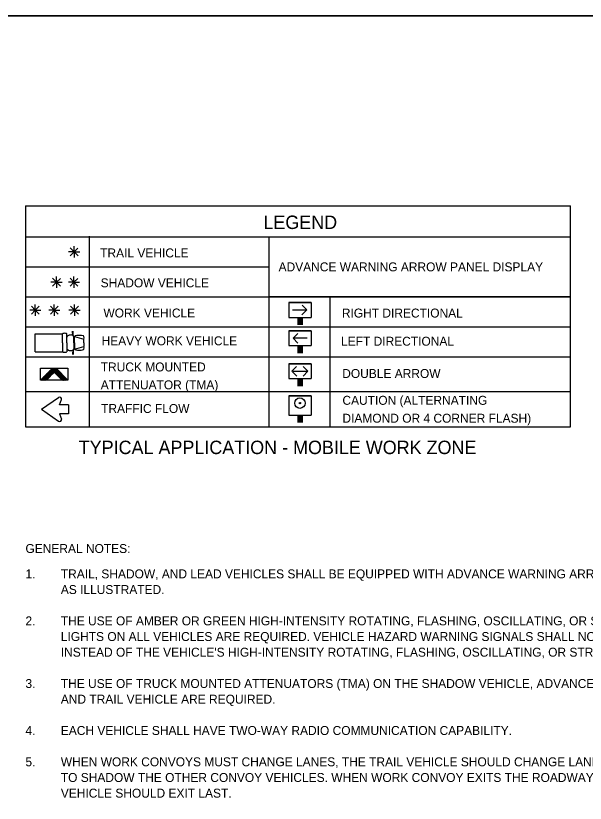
# Model space of a CAD drawing. Extents: x 1416408 to 1429341, y 372694 to 383211.
# Drawn here: x 1428120 to 1428760, y 373596 to 374480 of the extents above; entities that cross this region are included whole.
import ezdxf

# ---------------------------------------------------------------- set-up
doc = ezdxf.new("R2010")
doc.units = 0
for name, color, linetype in [('Default', 7, 'Continuous'), ('DSN_DRFT_Junk-No-Plot', 7, 'Continuous'), ('Working Level 1', 7, 'Continuous')]:
    doc.layers.add(name, color=color, linetype=linetype)

msp = doc.modelspace()

# ---------------------------------------------------------------- linework, layer by layer
at = {"layer": 'Default'}
for points in [[(1426234.86, 374479.9), (1426234.86, 372693.86), (1428995.11, 372693.86), (1428995.11, 374479.9)], [(1426234.86, 374479.9), (1426234.86, 372693.86), (1428995.11, 372693.86), (1428995.11, 374479.9)], [(1426234.86, 374479.9), (1428995.11, 374479.9), (1428995.11, 372693.86), (1426234.86, 372693.86)], [(1426234.86, 374479.9), (1426234.86, 372693.86), (1428995.11, 372693.86), (1428995.11, 374479.9)]]:
    msp.add_lwpolyline(points, close=True, dxfattribs=at)
at = {"layer": 'DSN_DRFT_Junk-No-Plot'}
msp.add_lwpolyline([(1426234.86, 374479.9), (1428995.11, 374479.9), (1428995.11, 372693.86), (1426234.86, 372693.86)], close=True, dxfattribs=at)
at = {"layer": 'Working Level 1'}
for p, q in [((1428130.66, 374266.62), (1428130.66, 374018.44)), ((1428130.66, 374266.62), (1428742.89, 374266.62)), ((1428742.89, 374018.44), (1428742.89, 374266.62)), ((1428130.66, 374231.78), (1428742.89, 374231.78)), ((1428202.33, 374232.37), (1428202.33, 374018.44)), ((1428202.33, 374232.37), (1428202.33, 374018.44)), ((1428404, 374231.78), (1428404, 374018.44)), ((1428185.42, 374214.79), (1428181.01, 374219.25)), ((1428185.31, 374214.71), (1428189.72, 374219.16)), ((1428185.42, 374214.79), (1428185.42, 374221.1)), ((1428185.42, 374214.79), (1428179.18, 374214.79)), ((1428185.42, 374214.79), (1428181.01, 374210.34)), ((1428185.42, 374214.79), (1428189.82, 374210.34)), ((1428185.42, 374214.79), (1428185.42, 374208.5)), ((1428185.42, 374214.79), (1428191.64, 374214.79)), ((1428130.66, 374198.11), (1428404, 374198.11)), ((1428165.58, 374180.75), (1428161.18, 374185.21)), ((1428165.49, 374180.66), (1428169.91, 374185.12)), ((1428165.58, 374180.75), (1428165.58, 374187.06)), ((1428185.18, 374180.75), (1428180.76, 374185.21)), ((1428185.09, 374180.67), (1428189.5, 374185.12)), ((1428185.18, 374180.75), (1428185.18, 374187.06)), ((1428165.58, 374180.75), (1428159.35, 374180.76)), ((1428165.58, 374180.75), (1428161.18, 374176.3)), ((1428165.58, 374180.75), (1428169.99, 374176.3)), ((1428165.58, 374180.75), (1428165.58, 374174.46)), ((1428165.58, 374180.75), (1428171.82, 374180.75)), ((1428185.18, 374180.75), (1428178.95, 374180.75)), ((1428185.18, 374180.75), (1428180.77, 374176.3)), ((1428185.18, 374180.75), (1428189.58, 374176.3)), ((1428185.18, 374180.75), (1428185.18, 374174.46)), ((1428185.18, 374180.75), (1428191.4, 374180.75)), ((1428130.66, 374164.45), (1428742.89, 374164.45)), ((1428742.89, 374164.45), (1428404, 374164.45)), ((1428472.51, 374164.45), (1428472.51, 374018.44)), ((1428141.72, 374149.38), (1428141.72, 374155.68)), ((1428163.08, 374149.38), (1428163.08, 374155.68)), ((1428185.82, 374149.38), (1428185.82, 374155.68)), ((1428426.57, 374157.92), (1428426.57, 374141.26)), ((1428451.5, 374157.92), (1428426.57, 374157.92)), ((1428426.57, 374157.92), (1428451.49, 374157.92)), ((1428451.5, 374157.92), (1428451.5, 374141.26)), ((1428141.72, 374149.38), (1428135.49, 374149.38)), ((1428141.72, 374149.38), (1428137.31, 374153.84)), ((1428141.72, 374149.38), (1428137.32, 374144.93)), ((1428141.63, 374149.28), (1428146.03, 374153.75)), ((1428141.72, 374149.38), (1428146.12, 374144.93)), ((1428141.72, 374149.38), (1428141.72, 374143.08)), ((1428141.72, 374149.38), (1428147.96, 374149.38)), ((1428163.08, 374149.38), (1428156.84, 374149.38)), ((1428163.08, 374149.38), (1428158.65, 374153.84)), ((1428163.08, 374149.38), (1428158.66, 374144.93)), ((1428162.98, 374149.28), (1428167.38, 374153.75)), ((1428163.08, 374149.38), (1428167.47, 374144.93)), ((1428163.08, 374149.38), (1428163.08, 374143.08)), ((1428163.08, 374149.38), (1428169.3, 374149.38)), ((1428185.82, 374149.38), (1428179.6, 374149.38)), ((1428185.82, 374149.38), (1428181.42, 374153.84)), ((1428185.82, 374149.38), (1428181.42, 374144.93)), ((1428185.73, 374149.28), (1428190.15, 374153.75)), ((1428185.82, 374149.38), (1428190.24, 374144.93)), ((1428185.82, 374149.38), (1428185.82, 374143.08)), ((1428185.82, 374149.38), (1428192.05, 374149.38)), ((1428430.79, 374149.6), (1428446.74, 374149.6)), ((1428446.74, 374149.6), (1428441.32, 374144.11)), ((1428446.74, 374149.6), (1428441.45, 374154.94)), ((1428426.57, 374141.26), (1428451.5, 374141.26)), ((1428436.54, 374141.26), (1428436.54, 374132.77)), ((1428437.78, 374141.26), (1428437.78, 374132.77)), ((1428439.03, 374141.26), (1428439.03, 374132.77)), ((1428440.28, 374141.26), (1428440.28, 374132.77)), ((1428441.53, 374141.26), (1428441.53, 374132.77)), ((1428130.66, 374130.78), (1428742.89, 374130.78)), ((1428130.66, 374130.78), (1428403.88, 374130.78)), ((1428141.72, 374122.81), (1428172.44, 374122.81)), ((1428141.72, 374102.72), (1428141.72, 374122.81)), ((1428172.44, 374112.76), (1428172.44, 374122.81)), ((1428177.15, 374112.76), (1428177.15, 374122.81)), ((1428183.49, 374123.4), (1428183.49, 374125.85)), ((1428183.88, 374121.03), (1428183.88, 374125.85)), ((1428184.2, 374121.03), (1428184.2, 374125.85)), ((1428426.57, 374126.21), (1428426.57, 374109.56)), ((1428451.5, 374126.21), (1428426.57, 374126.21)), ((1428426.57, 374126.21), (1428451.49, 374126.21)), ((1428431.32, 374117.89), (1428436.62, 374123.23)), ((1428451.5, 374126.21), (1428451.5, 374109.56)), ((1428172.44, 374112.76), (1428172.44, 374102.72)), ((1428177.15, 374112.76), (1428177.15, 374102.72)), ((1428185.05, 374112.76), (1428185.05, 374119.99)), ((1428185.05, 374112.76), (1428185.05, 374105.53)), ((1428185.69, 374119.99), (1428196.44, 374117.03)), ((1428185.69, 374112.76), (1428185.69, 374119.99)), ((1428185.69, 374112.76), (1428185.69, 374105.53)), ((1428196.44, 374112.76), (1428196.44, 374117.03)), ((1428196.44, 374112.76), (1428196.44, 374108.49)), ((1428447.27, 374117.89), (1428431.32, 374117.89)), ((1428431.32, 374117.89), (1428436.74, 374112.41)), ((1428141.72, 374102.72), (1428172.44, 374102.72)), ((1428183.88, 374104.48), (1428183.88, 374099.66)), ((1428184.2, 374104.48), (1428184.2, 374099.66)), ((1428185.69, 374105.53), (1428196.44, 374108.49)), ((1428426.57, 374109.56), (1428451.5, 374109.56)), ((1428436.54, 374109.56), (1428436.54, 374101.06)), ((1428437.78, 374109.56), (1428437.78, 374101.06)), ((1428439.03, 374109.56), (1428439.03, 374101.06)), ((1428440.28, 374109.56), (1428440.28, 374101.06)), ((1428441.53, 374109.56), (1428441.53, 374101.06)), ((1428130.66, 374097.11), (1428742.89, 374097.11)), ((1428183.49, 374102.13), (1428183.49, 374099.66)), ((1428426.57, 374089.23), (1428426.57, 374072.57)), ((1428451.5, 374089.23), (1428426.57, 374089.23)), ((1428426.57, 374089.23), (1428451.49, 374089.23)), ((1428430.07, 374080.9), (1428435.37, 374086.24)), ((1428447.99, 374080.9), (1428442.69, 374086.24)), ((1428451.5, 374089.23), (1428451.5, 374072.57)), ((1428147.53, 374070.78), (1428160.97, 374084.37)), ((1428154.26, 374070.78), (1428163.07, 374079.74)), ((1428171.93, 374070.78), (1428163.07, 374079.74)), ((1428178.39, 374070.87), (1428165.09, 374084.3)), ((1428430.07, 374080.9), (1428435.49, 374075.42)), ((1428431.32, 374080.9), (1428446.74, 374080.9)), ((1428447.99, 374080.9), (1428442.57, 374075.42)), ((1428426.57, 374072.57), (1428451.5, 374072.57)), ((1428436.54, 374072.57), (1428436.54, 374064.09)), ((1428437.78, 374072.57), (1428437.78, 374064.09)), ((1428439.03, 374072.57), (1428439.03, 374064.09)), ((1428440.28, 374072.57), (1428440.28, 374064.09)), ((1428441.53, 374072.57), (1428441.53, 374064.09)), ((1428130.66, 374057.98), (1428742.89, 374057.98)), ((1428148.66, 374038.1), (1428167.92, 374051.46)), ((1428426.57, 374053.39), (1428426.57, 374031.71)), ((1428451.5, 374053.39), (1428426.57, 374053.39)), ((1428426.57, 374053.39), (1428451.49, 374053.39)), ((1428451.5, 374053.39), (1428451.5, 374031.71)), ((1428169.13, 374043.2), (1428171.02, 374049.12)), ((1428179.18, 374043.2), (1428169.13, 374043.2)), ((1428179.18, 374043.2), (1428179.18, 374033)), ((1428148.66, 374038.1), (1428167.92, 374024.75)), ((1428179.18, 374033), (1428169.13, 374033)), ((1428169.13, 374033), (1428171.02, 374027.09)), ((1428426.57, 374031.71), (1428451.5, 374031.71)), ((1428436.54, 374031.71), (1428436.54, 374023.22)), ((1428437.78, 374031.71), (1428437.78, 374023.22)), ((1428439.03, 374031.71), (1428439.03, 374023.22)), ((1428440.28, 374031.71), (1428440.28, 374023.22)), ((1428441.53, 374031.71), (1428441.53, 374023.22)), ((1428130.66, 374018.44), (1428742.89, 374018.44))]:
    msp.add_line(p, q, dxfattribs=at)
msp.add_lwpolyline([(1428178.39, 374084.41), (1428178.39, 374070.78), (1428147.53, 374070.78), (1428147.53, 374084.41)], close=True, dxfattribs=at)
for points in [[(1428148.22, 374071.47), (1428166.95, 374082.4)], [(1428148.26, 374070.78), (1428162.4, 374079.03)], [(1428149.47, 374070.78), (1428160.82, 374077.41)], [(1428149.87, 374073.14), (1428166.51, 374082.86)], [(1428151.53, 374074.83), (1428166.06, 374083.31)], [(1428153.2, 374076.5), (1428165.62, 374083.76)], [(1428154.85, 374078.18), (1428165.18, 374084.21)], [(1428156.51, 374079.86), (1428164.15, 374084.32)], [(1428158.17, 374081.54), (1428162.95, 374084.34)], [(1428159.81, 374083.21), (1428161.79, 374084.35)], [(1428163.26, 374079.55), (1428167.4, 374081.96)], [(1428163.71, 374079.1), (1428167.84, 374081.51)], [(1428164.17, 374078.65), (1428168.28, 374081.05)], [(1428164.61, 374078.19), (1428168.73, 374080.6)], [(1428165.05, 374077.74), (1428169.18, 374080.15)], [(1428165.5, 374077.29), (1428169.62, 374079.7)], [(1428165.94, 374076.84), (1428170.06, 374079.25)], [(1428166.38, 374076.4), (1428170.5, 374078.8)], [(1428166.83, 374075.94), (1428170.94, 374078.34)], [(1428167.27, 374075.5), (1428171.4, 374077.9)], [(1428167.72, 374075.04), (1428171.84, 374077.45)], [(1428168.17, 374074.59), (1428172.28, 374077)], [(1428168.61, 374074.14), (1428172.72, 374076.54)], [(1428169.05, 374073.69), (1428173.17, 374076.08)], [(1428150.69, 374070.78), (1428159.24, 374075.76)], [(1428151.9, 374070.78), (1428157.65, 374074.13)], [(1428153.13, 374070.78), (1428156.06, 374072.5)], [(1428154.34, 374070.78), (1428154.48, 374070.87)], [(1428169.5, 374073.24), (1428173.62, 374075.64)], [(1428169.95, 374072.79), (1428174.05, 374075.2)], [(1428170.39, 374072.34), (1428174.5, 374074.74)], [(1428170.84, 374071.88), (1428174.94, 374074.28)], [(1428171.27, 374071.44), (1428175.39, 374073.84)], [(1428171.73, 374070.99), (1428175.82, 374073.38)], [(1428172.58, 374070.78), (1428176.28, 374072.94)], [(1428173.81, 374070.78), (1428176.72, 374072.49)], [(1428175.03, 374070.78), (1428177.17, 374072.03)], [(1428176.24, 374070.78), (1428177.62, 374071.58)], [(1428177.46, 374070.78), (1428178.05, 374071.13)]]:
    msp.add_lwpolyline(points, dxfattribs=at)
for centre, major_axis, ratio, start_param, end_param in [((1428174.8, 374122.79), (2.35, 0), 0.272891, 6.283185, 9.424778), ((1428181.1, 374119.49), (3.94, 0.5), 0.50847, 6.28135, 9.422943), ((1428191.07, 374119.93), (5.37, -0.06), 0.205643, 0.000054, 3.141647), ((1428193.81, 374118.44), (0, 3.01), 0.989089, 4.221603, 5.203174), ((1428174.8, 374102.73), (2.35, 0), 0.272891, 3.141593, 6.283185), ((1428181.1, 374106.03), (3.94, -0.5), 0.50847, 3.143427, 6.28502), ((1428191.07, 374105.6), (5.37, 0.06), 0.205643, 3.141539, 6.283131), ((1428193.81, 374107.08), (0, 3.01), 0.989089, 4.221604, 5.203174), ((1428169.08, 374049.76), (0, -2.06), 0.989089, 1.259821, 3.74278), ((1428169.08, 374026.44), (0, -2.06), 0.989089, 5.681999, 8.164958)]:
    msp.add_ellipse(centre, major_axis=major_axis, ratio=ratio, start_param=start_param, end_param=end_param, dxfattribs=at)
for major_axis in [(0, 5.88), (0, 0.732)]:
    msp.add_ellipse((1428439.03, 374045.06), major_axis=major_axis, ratio=0.989089, dxfattribs=at)

# ---------------------------------------------------------------- texts
for s, height, p in [('LEGEND', 15.07, (1428397.98, 374240.5)), ('TRAIL VEHICLE', 10.0465, (1428214.63, 374208.61)), ('ADVANCE WARNING ARROW PANEL DISPLAY', 10.0465, (1428415.08, 374192.97)), ('SHADOW VEHICLE', 10.0465, (1428215.21, 374175.05)), ('WORK VEHICLE', 10.0465, (1428218.31, 374141.19)), ('RIGHT DIRECTIONAL', 10.0465, (1428486.15, 374141.13)), ('HEAVY WORK VEHICLE', 10.0465, (1428216.22, 374109.98)), ('LEFT DIRECTIONAL', 10.0465, (1428485.24, 374109.5)), ('TRUCK MOUNTED ', 10.0465, (1428215.28, 374080.64)), ('DOUBLE ARROW', 10.0465, (1428486.55, 374073.27)), ('ATTENUATOR (TMA)', 10.0465, (1428215.28, 374060.55)), ('CAUTION (ALTERNATING ', 10.0465, (1428486.79, 374043.16)), ('TRAFFIC FLOW', 10.0465, (1428215.71, 374033.97)), ('DIAMOND OR 4 CORNER FLASH)', 10.0465, (1428486.79, 374023.07)), ('TYPICAL APPLICATION - MOBILE WORK ZONE', 15.0697, (1428190.54, 373987.82)), ('GENERAL NOTES:', 10.0465, (1428130.69, 373876.8)), ('1. ', 10.046, (1428130.69, 373848.33)), ('TRAIL, SHADOW, AND LEAD VEHICLES SHALL BE EQUIPPED WITH ADVANCE WARNING ARROW PANELS', 10.0465, (1428170.44, 373848.33)), ('AS ILLUSTRATED. ', 10.0465, (1428170.44, 373830.75)), ('2.', 10.046, (1428130.69, 373795.58)), ('THE USE OF AMBER OR GREEN HIGH-INTENSITY ROTATING, FLASHING, OSCILLATING, OR STROBE ', 10.0465, (1428170.44, 373795.58)), ('LIGHTS ON ALL VEHICLES ARE REQUIRED. VEHICLE HAZARD WARNING SIGNALS SHALL NOT BE USED ', 10.0465, (1428170.44, 373778)), ("INSTEAD OF THE VEHICLE'S HIGH-INTENSITY ROTATING, FLASHING, OSCILLATING, OR STROBE LIGHTS.", 10.0465, (1428170.44, 373760.42)), ('3. ', 10.046, (1428130.69, 373725.26)), ('THE USE OF TRUCK MOUNTED ATTENUATORS (TMA) ON THE SHADOW VEHICLE, ADVANCE WARNING', 10.0465, (1428170.44, 373725.26)), ('AND TRAIL VEHICLE ARE REQUIRED.', 10.0465, (1428170.44, 373707.68)), ('4. ', 10.046, (1428130.69, 373672.52)), ('EACH VEHICLE SHALL HAVE TWO-WAY RADIO COMMUNICATION CAPABILITY. ', 10.0465, (1428170.44, 373672.52)), ('5. ', 10.046, (1428130.69, 373637.35)), ('WHEN WORK CONVOYS MUST CHANGE LANES, THE TRAIL VEHICLE SHOULD CHANGE LANES FIRST ', 10.0465, (1428170.44, 373637.35)), ('TO SHADOW THE OTHER CONVOY VEHICLES. WHEN WORK CONVOY EXITS THE ROADWAY, THE TRAIL', 10.0465, (1428170.44, 373619.77)), ('VEHICLE SHOULD EXIT LAST.', 10.0465, (1428170.44, 373602.19))]:
    msp.add_text(s, height=height, dxfattribs=at).set_placement(p)

doc.saveas('drawing.dxf')
